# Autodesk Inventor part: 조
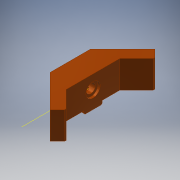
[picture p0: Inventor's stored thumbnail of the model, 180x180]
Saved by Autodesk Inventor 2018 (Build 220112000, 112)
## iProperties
Created: 2019-04
Part Number: 조
Material: 알루미늄 6061
Document SubType Name: Modeling
Designer: mduedu
Density: 1 g/cm^3
Appearance: Smooth - Light Orange
Author: mduedu
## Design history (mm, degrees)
sketch "스케치1"
  geometry: L1 (45.962, 0)-(0, -45.962); L2 (0, -45.962)-(-45.962, 0); L3 (-45.962, 0)-(0, 45.962); L4 (0, 45.962)-(45.962, 0); L5 (45.962, 0)-(-45.962, 0); L6 (0, -45.962)-(0, 45.962); 1 further point
  constraints: 12 end point, 2 midpoint, 2 parallel, 2 perpendicular, 1 horizontal
  dimensions: "d0" = 65 distance of L1.end L2.end
extrude "돌출1" new body sketch "스케치1" distance "d2" = 27; taper "d3" = 0 deg
chamfer "모따기1" distance "d4" = 25; stored, may be unused: second distance "d5" = 2, angle "d6" = 45 deg
sketch "스케치2"
  geometry: L1 (-17.678, 28.284)-(-45.962, 0) reference; L2 (-17.678, 28.284)-(17.678, 28.284) reference; L3 (45.962, 0)-(17.678, 28.284) reference; L4 (-45.962, 0)-(0, -45.962) reference; L5 (0, -45.962)-(45.962, 0) reference; L6 (-23.536, 8.284)-(23.536, 8.284); L7 (-23.536, 8.284)-(-38.891, -7.071); L8 (38.891, -7.071)-(23.536, 8.284); 1 further point
  constraints: 6 end point, 3 parallel, 2 point on line
  dimensions: "d7" = 20 distance between parallel lines of L6 L2; "d8" = 10 distance between parallel lines of L1 L7; "d9" = 10 distance between parallel lines of L3 L8
extrude "돌출2" cut sketch "스케치2" extent not by distance; stored distance "d10" = 27; taper "d11" = 0 deg
sketch "스케치3"
  geometry: L1 (63.64, -27)-(63.64, 0) reference; L2 (56.569, -27)-(63.64, -27) reference; L3 (-28.284, -27)-(-28.284, 0) reference; L4 (-28.284, -27)-(-21.213, -27) reference; L5 (63.64, -27)-(25.678, -27); L6 (25.678, -27)-(25.678, -24); L7 (25.678, -24)-(63.64, -24); L8 (63.64, -24)-(63.64, -27); L9 (-28.284, -27)-(9.678, -27); L10 (9.678, -27)-(9.678, -24); L11 (9.678, -24)-(-28.284, -24); L12 (-28.284, -24)-(-28.284, -27); L13 (41.213, 0)-(-5.858, 0) reference; L14 (17.678, -27)-(17.678, 0)
  constraints: 18 end point, 4 parallel, 2 horizontal, 2 perpendicular, 1 midpoint, 1 symmetric about line
  dimensions: "d12" = 3 distance between parallel lines of L5 L7; "d14" = 16 distance between parallel lines of L10 L6
extrude "돌출3" cut sketch "스케치3" extent not by distance; stored distance "d15" = 27; taper "d16" = 0 deg
sketch "스케치4"
  geometry: L1 (31.536, -27)-(15.536, -27) reference; L2 (31.536, -24)-(47.071, -24) reference; 3 further points
  constraints: 1 midpoint, 1 vertical alignment
  dimensions: "d17" = 12 distance from line of L2 point (23.536, -12)
hole "구멍1" sketch "스케치4" at (23.536, -12) diameter "d18" = 8; stored, may be unused: countersink angle "d22" = 90 deg, drill point angle "d24" = 118 deg; dims "d19" = 6, "d20" = 12.5, "d21" = 2, "d23" = 14
node "작업 평면1"
sketch "스케치5"
  geometry: L1 (0, -15)-(0, 0); L2 (-50, -4)-(50, -4); L3 (50, -4)-(50, -1.75); L4 (-50, -1.75)-(-50, -4); L5 (12, -1.75)-(12, -2.75); L6 (12, -2.75)-(-12, -2.75); L7 (-12, -2.75)-(-12, -1.75); L8 (50, -1.75)-(12, -1.75); L9 (-12, -1.75)-(-50, -1.75); C1 r 4 at (0, 0) reference; 2 further points
  constraints: 18 end point, 4 parallel, 2 midpoint, 2 vertical, 2 vertical alignment, 1 collinear, 1 horizontal, 1 perpendicular, 1 tangent
  dimensions: "d26" = 2.5 diameter of L6 L2; "d28" = 4.5 diameter of L8 L2; "d29" = 24 distance of L5.end L6.end; "d30" = 100 distance between parallel lines of L3 L4
revolve "회전1" sketch "스케치5" stored, may be unused: angle "d31" = 90 deg
chamfer "모따기2" distance "d32" = 1; stored, may be unused: second distance "d33" = 2, angle "d34" = 45 deg
chamfer "모따기3" distance "d35" = 1; stored, may be unused: second distance "d36" = 2, angle "d37" = 45 deg
node "작업축1"
node "솔리드1"
other parameters: "d25" = -5
